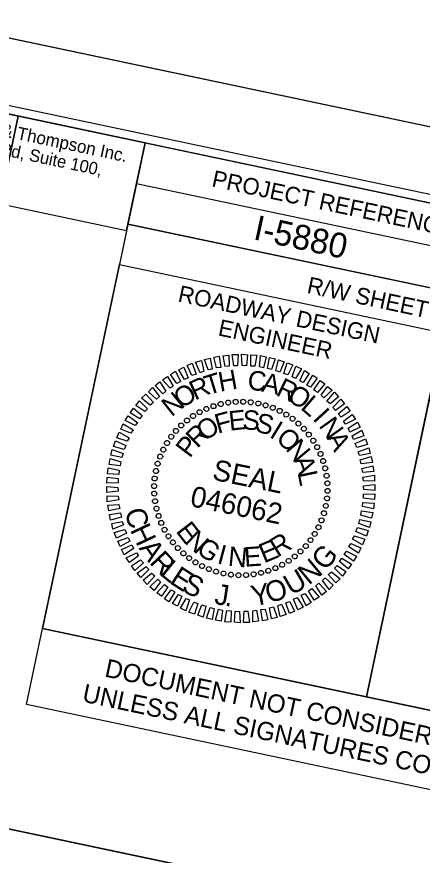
# Model space of a CAD drawing. Extents: x 1636389 to 1804395, y 659763 to 844521.
# Drawn here: x 1638006.9 to 1638129.5, y 843981.4 to 844234.9 of the extents above; entities that cross this region are included whole.
import ezdxf

# ---------------------------------------------------------------- set-up
doc = ezdxf.new("R2010")
doc.units = 0
for name, color, linetype in [('Default', 7, 'Continuous'), ('Old_Level_2', 7, 'Continuous'), ('Prop Dimension Text', 7, 'Continuous'), ('Sheet Clip Boundary CELL', 7, 'Continuous'), ('Sheet Cutting Line CELL', 7, 'Continuous'), ('Sheet Data Field CELL', 7, 'Continuous'), ('Sheet Plan CELL', 7, 'Continuous'), ('Sheet Plan Layout CELL', 7, 'Continuous'), ('Sheet Plot Border Inside CELL', 7, 'Continuous'), ('Sheet Plot Border Outside CELL', 7, 'Continuous'), ('Sheet Sticker Exception Certification CELL', 7, 'Continuous')]:
    doc.layers.add(name, color=color, linetype=linetype)

msp = doc.modelspace()

# ---------------------------------------------------------------- linework, layer by layer
at = {"layer": 'Old_Level_2'}
for p, q in [((1638068.56, 844117.84), (1638068.56, 844117.84)), ((1638070.77, 844118.28), (1638070.77, 844118.28)), ((1638073.04, 844118.49), (1638073.04, 844118.49)), ((1638075.38, 844118.48), (1638075.38, 844118.48)), ((1638077.65, 844118.37), (1638077.65, 844118.37)), ((1638079.92, 844118), (1638079.92, 844118)), ((1638062.15, 844115.42), (1638062.15, 844115.42)), ((1638064.19, 844116.37), (1638064.19, 844116.37)), ((1638066.36, 844117.18), (1638066.36, 844117.18)), ((1638082.15, 844117.43), (1638082.15, 844117.43)), ((1638084.29, 844116.66), (1638084.29, 844116.66)), ((1638086.37, 844115.79), (1638086.37, 844115.79)), ((1638058.32, 844112.89), (1638058.32, 844112.89)), ((1638060.16, 844114.19), (1638060.16, 844114.19)), ((1638088.39, 844114.67), (1638088.39, 844114.67)), ((1638090.27, 844113.36), (1638090.27, 844113.36)), ((1638056.6, 844111.35), (1638056.6, 844111.35)), ((1638092.09, 844111.96), (1638092.09, 844111.96)), ((1638093.7, 844110.33), (1638093.7, 844110.33)), ((1638053.57, 844107.92), (1638053.57, 844107.92)), ((1638054.97, 844109.73), (1638054.97, 844109.73)), ((1638095.24, 844108.6), (1638095.24, 844108.6)), ((1638052.26, 844106.04), (1638052.26, 844106.04)), ((1638096.54, 844106.76), (1638096.54, 844106.76)), ((1638051.14, 844104.01), (1638051.14, 844104.01)), ((1638097.77, 844104.78), (1638097.77, 844104.78)), ((1638098.72, 844102.74), (1638098.72, 844102.74)), ((1638050.27, 844101.94), (1638050.27, 844101.94)), ((1638099.54, 844100.57), (1638099.54, 844100.57)), ((1638048.92, 844097.57), (1638048.92, 844097.57)), ((1638049.5, 844099.8), (1638049.5, 844099.8)), ((1638100.19, 844098.37), (1638100.19, 844098.37)), ((1638048.55, 844095.29), (1638048.55, 844095.29)), ((1638100.63, 844096.16), (1638100.63, 844096.16)), ((1638048.45, 844093.03), (1638048.45, 844093.03)), ((1638074.64, 844092.29), (1638074.64, 844092.29)), ((1638100.84, 844093.89), (1638100.84, 844093.89)), ((1638048.44, 844090.69), (1638048.44, 844090.69)), ((1638100.83, 844091.55), (1638100.83, 844091.55)), ((1638048.65, 844088.41), (1638048.65, 844088.41)), ((1638100.73, 844089.28), (1638100.73, 844089.28)), ((1638049.09, 844086.2), (1638049.09, 844086.2)), ((1638099.78, 844084.78), (1638099.78, 844084.78)), ((1638100.36, 844087.01), (1638100.36, 844087.01)), ((1638049.74, 844084.01), (1638049.74, 844084.01)), ((1638099.01, 844082.63), (1638099.01, 844082.63)), ((1638050.56, 844081.83), (1638050.56, 844081.83)), ((1638051.51, 844079.8), (1638051.51, 844079.8)), ((1638098.14, 844080.56), (1638098.14, 844080.56)), ((1638052.74, 844077.81), (1638052.74, 844077.81)), ((1638097.02, 844078.54), (1638097.02, 844078.54)), ((1638054.04, 844075.97), (1638054.04, 844075.97)), ((1638094.31, 844074.84), (1638094.31, 844074.84)), ((1638095.71, 844076.65), (1638095.71, 844076.65)), ((1638055.58, 844074.25), (1638055.58, 844074.25)), ((1638057.19, 844072.62), (1638057.19, 844072.62)), ((1638092.68, 844073.23), (1638092.68, 844073.23)), ((1638059, 844071.22), (1638059, 844071.22)), ((1638060.89, 844069.91), (1638060.89, 844069.91)), ((1638089.12, 844070.38), (1638089.12, 844070.38)), ((1638090.95, 844071.69), (1638090.95, 844071.69)), ((1638062.91, 844068.78), (1638062.91, 844068.78)), ((1638064.99, 844067.92), (1638064.99, 844067.92)), ((1638067.13, 844067.15), (1638067.13, 844067.15)), ((1638082.92, 844067.39), (1638082.92, 844067.39)), ((1638085.09, 844068.21), (1638085.09, 844068.21)), ((1638087.13, 844069.16), (1638087.13, 844069.16)), ((1638069.36, 844066.57), (1638069.36, 844066.57)), ((1638071.63, 844066.2), (1638071.63, 844066.2)), ((1638073.9, 844066.1), (1638073.9, 844066.1)), ((1638076.24, 844066.08), (1638076.24, 844066.08)), ((1638078.51, 844066.3), (1638078.51, 844066.3)), ((1638080.72, 844066.74), (1638080.72, 844066.74))]:
    msp.add_line(p, q, dxfattribs=at)
for points in [[(1638075.08, 844129.44), (1638074.88, 844132.88), (1638076.6, 844132.72), (1638076.35, 844129.36)], [(1638062.34, 844127.29), (1638060.96, 844130.43), (1638062.71, 844130.95), (1638063.44, 844127.73)], [(1638064.78, 844128.12), (1638063.68, 844131.3), (1638065.4, 844131.72), (1638066, 844128.37)], [(1638067.25, 844128.77), (1638066.47, 844132), (1638068.12, 844132.33), (1638068.59, 844128.84)], [(1638069.92, 844129.13), (1638069.31, 844132.43), (1638070.99, 844132.6), (1638071.07, 844129.28)], [(1638072.51, 844129.33), (1638072.04, 844132.77), (1638073.85, 844132.81), (1638073.64, 844129.39)], [(1638077.61, 844129.29), (1638077.66, 844132.68), (1638079.44, 844132.56), (1638078.87, 844129.21)], [(1638080.23, 844129.06), (1638080.59, 844132.45), (1638082.28, 844132.08), (1638081.45, 844128.78)], [(1638082.68, 844128.55), (1638083.31, 844131.89), (1638085, 844131.52), (1638083.91, 844128.27)], [(1638085.23, 844127.92), (1638086.06, 844131.22), (1638087.69, 844130.59), (1638086.42, 844127.48)], [(1638057.6, 844125.25), (1638055.85, 844128.13), (1638057.44, 844128.95), (1638058.7, 844125.74)], [(1638059.84, 844126.43), (1638058.43, 844129.41), (1638059.95, 844130.14), (1638061.09, 844126.84)], [(1638087.62, 844127.05), (1638088.69, 844130.25), (1638090.34, 844129.68), (1638088.82, 844126.66)], [(1638090.13, 844125.99), (1638091.27, 844129.24), (1638092.94, 844128.5), (1638091.16, 844125.53)], [(1638092.48, 844124.86), (1638093.84, 844127.91), (1638095.34, 844127.09), (1638093.49, 844124.3)], [(1638053.22, 844122.56), (1638050.99, 844125.16), (1638052.49, 844126.1), (1638054.19, 844123.23)], [(1638055.25, 844124.04), (1638053.41, 844126.73), (1638054.87, 844127.73), (1638056.36, 844124.58)], [(1638094.62, 844123.51), (1638096.4, 844126.52), (1638097.73, 844125.64), (1638095.73, 844122.92)], [(1638049.15, 844119.28), (1638046.7, 844121.54), (1638047.95, 844122.85), (1638050, 844120.13)], [(1638051.05, 844120.94), (1638048.75, 844123.45), (1638050.13, 844124.57), (1638051.94, 844121.74)], [(1638096.75, 844122.1), (1638098.6, 844124.89), (1638100.06, 844123.87), (1638097.77, 844121.32)], [(1638098.89, 844120.47), (1638100.82, 844123.14), (1638102.2, 844121.98), (1638099.75, 844119.67)], [(1638047.22, 844117.51), (1638044.63, 844119.59), (1638045.93, 844120.84), (1638048.22, 844118.28)], [(1638100.64, 844118.71), (1638102.99, 844121.36), (1638104.13, 844120.03), (1638101.65, 844117.88)], [(1638045.57, 844115.53), (1638042.88, 844117.36), (1638043.95, 844118.81), (1638046.37, 844116.39)], [(1638102.46, 844116.78), (1638104.88, 844119.25), (1638106.01, 844117.87), (1638103.3, 844115.87)], [(1638044.1, 844113.36), (1638041.14, 844115.14), (1638042.21, 844116.59), (1638044.83, 844114.39)], [(1638104.11, 844114.82), (1638106.72, 844117.1), (1638107.72, 844115.63), (1638104.94, 844113.86)], [(1638042.65, 844111.29), (1638039.64, 844112.81), (1638040.61, 844114.28), (1638043.42, 844112.26)], [(1638105.63, 844112.67), (1638108.29, 844114.68), (1638109.29, 844113.21), (1638106.24, 844111.71)], [(1638041.42, 844108.97), (1638038.36, 844110.23), (1638039.04, 844111.86), (1638042.04, 844109.97)], [(1638107.08, 844110.49), (1638109.88, 844112.36), (1638110.7, 844110.77), (1638107.61, 844109.33)], [(1638040.29, 844106.62), (1638037.18, 844107.63), (1638037.87, 844109.31), (1638040.91, 844107.63)], [(1638108.25, 844108.19), (1638111.17, 844109.88), (1638111.87, 844108.21), (1638108.68, 844107.1)], [(1638039.39, 844104.08), (1638036.16, 844105), (1638036.69, 844106.71), (1638039.88, 844105.26)], [(1638109.19, 844105.84), (1638112.28, 844107.28), (1638112.97, 844105.56), (1638109.72, 844104.68)], [(1638038.68, 844101.66), (1638035.35, 844102.39), (1638035.77, 844104.06), (1638039.01, 844102.87)], [(1638110.1, 844103.33), (1638113.32, 844104.59), (1638113.69, 844102.87), (1638110.54, 844102.24)], [(1638038.15, 844099.1), (1638034.78, 844099.57), (1638035.1, 844101.32), (1638038.38, 844100.33)], [(1638110.72, 844100.92), (1638114.04, 844101.9), (1638114.4, 844100.13), (1638111.02, 844099.7)], [(1638037.72, 844096.52), (1638034.3, 844096.73), (1638034.52, 844098.5), (1638037.84, 844097.77)], [(1638111.19, 844098.34), (1638114.58, 844099.09), (1638114.85, 844097.39), (1638111.51, 844097.16)], [(1638037.56, 844093.99), (1638034.09, 844093.9), (1638034.26, 844095.67), (1638037.59, 844095.27)], [(1638111.56, 844095.72), (1638115.07, 844096.28), (1638115.06, 844094.53), (1638111.71, 844094.57)], [(1638037.57, 844091.44), (1638034.15, 844091.07), (1638034.16, 844092.87), (1638037.46, 844092.58)], [(1638111.71, 844093.13), (1638115.13, 844093.51), (1638115.12, 844091.7), (1638111.82, 844092)], [(1638037.72, 844088.86), (1638034.21, 844088.29), (1638034.22, 844090.04), (1638037.56, 844090)], [(1638111.71, 844090.58), (1638115.19, 844090.68), (1638115.02, 844088.9), (1638111.69, 844089.31)], [(1638038.09, 844086.24), (1638034.7, 844085.49), (1638034.43, 844087.19), (1638037.77, 844087.41)], [(1638111.56, 844088.05), (1638114.98, 844087.84), (1638114.76, 844086.08), (1638111.44, 844086.8)], [(1638038.56, 844083.65), (1638035.24, 844082.67), (1638034.88, 844084.44), (1638038.26, 844084.88)], [(1638111.13, 844085.48), (1638114.5, 844085.01), (1638114.18, 844083.26), (1638110.9, 844084.24)], [(1638039.18, 844081.25), (1638035.96, 844079.99), (1638035.59, 844081.7), (1638038.74, 844082.34)], [(1638110.6, 844082.91), (1638113.92, 844082.19), (1638113.51, 844080.51), (1638110.27, 844081.7)], [(1638040.09, 844078.74), (1638037, 844077.29), (1638036.31, 844079.02), (1638039.56, 844079.9)], [(1638109.89, 844080.5), (1638113.12, 844079.57), (1638112.59, 844077.86), (1638109.4, 844079.31)], [(1638041.03, 844076.38), (1638038.11, 844074.69), (1638037.41, 844076.36), (1638040.6, 844077.47)], [(1638108.99, 844077.95), (1638112.1, 844076.94), (1638111.41, 844075.26), (1638108.37, 844076.95)], [(1638042.2, 844074.09), (1638039.4, 844072.21), (1638038.58, 844073.8), (1638041.67, 844075.25)], [(1638107.86, 844075.61), (1638110.92, 844074.35), (1638110.24, 844072.72), (1638107.24, 844074.61)], [(1638043.65, 844071.9), (1638040.99, 844069.9), (1638039.99, 844071.36), (1638043.04, 844072.87)], [(1638106.62, 844073.29), (1638109.64, 844071.77), (1638108.67, 844070.3), (1638105.86, 844072.31)], [(1638045.17, 844069.76), (1638042.56, 844067.48), (1638041.56, 844068.94), (1638044.34, 844070.71)], [(1638105.17, 844071.22), (1638108.14, 844069.44), (1638107.07, 844067.99), (1638104.45, 844070.18)], [(1638046.82, 844067.8), (1638044.39, 844065.33), (1638043.27, 844066.71), (1638045.98, 844068.7)], [(1638102.06, 844067.06), (1638104.65, 844064.98), (1638103.35, 844063.74), (1638101.06, 844066.29)], [(1638103.71, 844069.04), (1638106.4, 844067.21), (1638105.33, 844065.76), (1638102.91, 844068.18)], [(1638048.64, 844065.86), (1638046.29, 844063.22), (1638045.15, 844064.55), (1638047.63, 844066.69)], [(1638050.39, 844064.1), (1638048.45, 844061.43), (1638047.08, 844062.59), (1638049.53, 844064.9)], [(1638100.13, 844065.29), (1638102.58, 844063.03), (1638101.33, 844061.72), (1638099.28, 844064.44)], [(1638052.53, 844062.48), (1638050.68, 844059.68), (1638049.22, 844060.7), (1638051.51, 844063.25)], [(1638096.06, 844062.01), (1638098.29, 844059.42), (1638096.79, 844058.47), (1638095.09, 844061.34)], [(1638098.23, 844063.63), (1638100.53, 844061.13), (1638099.15, 844060), (1638097.33, 844062.84)], [(1638054.66, 844061.07), (1638052.88, 844058.05), (1638051.55, 844058.94), (1638053.55, 844061.65)], [(1638056.8, 844059.71), (1638055.44, 844056.67), (1638053.94, 844057.48), (1638055.79, 844060.27)], [(1638094.03, 844060.53), (1638095.87, 844057.85), (1638094.41, 844056.84), (1638092.92, 844059.99)], [(1638059.15, 844058.58), (1638058.01, 844055.34), (1638056.34, 844056.08), (1638058.12, 844059.04)], [(1638061.66, 844057.53), (1638060.59, 844054.33), (1638058.94, 844054.9), (1638060.46, 844057.91)], [(1638064.05, 844056.66), (1638063.22, 844053.35), (1638061.59, 844053.98), (1638062.86, 844057.09)], [(1638086.94, 844057.28), (1638088.32, 844054.15), (1638086.57, 844053.62), (1638085.84, 844056.84)], [(1638089.44, 844058.14), (1638090.85, 844055.17), (1638089.33, 844054.44), (1638088.19, 844057.74)], [(1638091.68, 844059.32), (1638093.43, 844056.44), (1638091.84, 844055.62), (1638090.58, 844058.83)], [(1638066.59, 844056.02), (1638065.97, 844052.68), (1638064.28, 844053.05), (1638065.37, 844056.3)], [(1638069.05, 844055.51), (1638068.69, 844052.12), (1638067, 844052.49), (1638067.83, 844055.79)], [(1638071.67, 844055.29), (1638071.62, 844051.89), (1638069.84, 844052.01), (1638070.41, 844055.36)], [(1638074.19, 844055.14), (1638074.4, 844051.69), (1638072.68, 844051.86), (1638072.93, 844055.21)], [(1638076.77, 844055.24), (1638077.24, 844051.8), (1638075.43, 844051.77), (1638075.64, 844055.19)], [(1638079.36, 844055.45), (1638079.97, 844052.14), (1638078.29, 844051.98), (1638078.21, 844055.29)], [(1638082.03, 844055.8), (1638082.81, 844052.57), (1638081.15, 844052.24), (1638080.69, 844055.73)], [(1638084.49, 844056.46), (1638085.6, 844053.27), (1638083.87, 844052.85), (1638083.28, 844056.21)]]:
    msp.add_lwpolyline(points, close=True, dxfattribs=at)
for centre, major_axis in [((1638066.35, 844117.17), (-0.238, 0.714)), ((1638068.55, 844117.8), (-0.175, 0.732)), ((1638070.8, 844118.23), (-0.11, 0.745)), ((1638073.07, 844118.47), (-0.045, 0.752)), ((1638075.36, 844118.5), (0.021, 0.753)), ((1638077.64, 844118.34), (0.086, 0.748)), ((1638079.9, 844117.98), (0.151, 0.738)), ((1638082.12, 844117.43), (0.215, 0.722)), ((1638062.15, 844115.35), (-0.358, 0.662)), ((1638064.21, 844116.35), (-0.299, 0.691)), ((1638084.28, 844116.68), (0.277, 0.7)), ((1638086.37, 844115.74), (0.337, 0.673)), ((1638088.37, 844114.63), (0.394, 0.641)), ((1638058.34, 844112.83), (-0.468, 0.59)), ((1638060.19, 844114.18), (-0.415, 0.628)), ((1638090.27, 844113.35), (0.449, 0.605)), ((1638092.04, 844111.91), (0.5, 0.563)), ((1638055.02, 844109.69), (-0.563, 0.5)), ((1638056.61, 844111.33), (-0.518, 0.547)), ((1638093.69, 844110.32), (0.547, 0.518)), ((1638053.58, 844107.91), (-0.605, 0.449)), ((1638095.19, 844108.59), (0.59, 0.468)), ((1638096.53, 844106.74), (0.628, 0.415)), ((1638052.29, 844106.02), (-0.641, 0.394)), ((1638097.71, 844104.77), (0.662, 0.358)), ((1638050.25, 844101.93), (-0.7, 0.277)), ((1638051.18, 844104.02), (-0.673, 0.337)), ((1638098.71, 844102.71), (0.691, 0.299)), ((1638049.5, 844099.77), (-0.722, 0.215)), ((1638099.52, 844100.58), (0.714, 0.238)), ((1638048.95, 844097.55), (-0.738, 0.151)), ((1638100.15, 844098.38), (0.732, 0.175)), ((1638048.58, 844095.29), (-0.748, 0.086)), ((1638100.58, 844096.13), (0.745, 0.11)), ((1638048.42, 844093.01), (-0.753, 0.021)), ((1638100.82, 844093.86), (0.752, 0.045)), ((1638100.86, 844091.57), (0.753, -0.021)), ((1638048.46, 844090.72), (-0.752, -0.045)), ((1638100.7, 844089.28), (0.748, -0.086)), ((1638048.7, 844088.44), (-0.745, -0.11)), ((1638100.33, 844087.03), (0.738, -0.151)), ((1638049.13, 844086.2), (-0.732, -0.175)), ((1638049.76, 844084), (-0.714, -0.238)), ((1638099.78, 844084.81), (0.722, -0.215)), ((1638050.57, 844081.86), (-0.691, -0.299)), ((1638099.03, 844082.64), (0.7, -0.277)), ((1638051.57, 844079.8), (-0.662, -0.358)), ((1638098.1, 844080.55), (0.673, -0.337)), ((1638052.75, 844077.84), (-0.628, -0.415)), ((1638095.7, 844076.66), (0.605, -0.449)), ((1638096.99, 844078.55), (0.641, -0.394)), ((1638054.09, 844075.99), (-0.59, -0.468)), ((1638055.59, 844074.26), (-0.547, -0.518)), ((1638094.26, 844074.88), (0.563, -0.5)), ((1638057.24, 844072.67), (-0.5, -0.563)), ((1638059.01, 844071.22), (-0.449, -0.605)), ((1638090.94, 844071.74), (0.468, -0.59)), ((1638092.67, 844073.24), (0.518, -0.547)), ((1638060.91, 844069.94), (-0.394, -0.641)), ((1638062.91, 844068.83), (-0.337, -0.673)), ((1638087.13, 844069.22), (0.358, -0.662)), ((1638089.09, 844070.4), (0.415, -0.628)), ((1638065, 844067.9), (-0.277, -0.7)), ((1638067.16, 844067.15), (-0.215, -0.722)), ((1638069.38, 844066.59), (-0.151, -0.738)), ((1638071.64, 844066.23), (-0.086, -0.748)), ((1638078.48, 844066.34), (0.11, -0.745)), ((1638080.73, 844066.78), (0.175, -0.732)), ((1638082.93, 844067.4), (0.238, -0.714)), ((1638085.07, 844068.22), (0.299, -0.691)), ((1638073.92, 844066.07), (-0.021, -0.753)), ((1638076.21, 844066.11), (0.045, -0.752))]:
    msp.add_ellipse(centre, major_axis=major_axis, ratio=0.999708, dxfattribs=at)
at = {"layer": 'Prop Dimension Text'}
msp.add_lwpolyline([(1637893.3, 844201.3), (1638040.08, 844170.28), (1638045.68, 844196.77), (1637898.89, 844227.79)], close=True, dxfattribs=at)
at = {"layer": 'Sheet Clip Boundary CELL'}
msp.add_lwpolyline([(1636605.88, 843427.4), (1637975.74, 843138.4), (1637933.22, 843216.08), (1637972.57, 843309.02), (1638006.91, 843302.19), (1638028.95, 843389.18), (1638110.62, 843766.5), (1638114.85, 843806.98), (1638084.44, 843843.65), (1637963.65, 843997.92), (1638007.31, 844204.85), (1636822.64, 844454.79)], close=True, dxfattribs=at)
at = {"layer": 'Sheet Cutting Line CELL'}
msp.add_line((1638262.69, 844173.95), (1636615.46, 844521.48), dxfattribs=at)
at = {"layer": 'Sheet Plan CELL'}
for p, q in [((1638043.08, 844184.49), (1638238.82, 844143.18)), ((1638040.5, 844172.22), (1638037.92, 844160)), ((1638040.5, 844172.22), (1638236.24, 844130.95)), ((1638040.5, 844172.22), (1638236.24, 844130.95)), ((1638135.82, 844139.35), (1638112.61, 844029.31))]:
    msp.add_line(p, q, dxfattribs=at)
for points in [[(1638241.44, 844155.45), (1636773.71, 844465.11), (1636556.96, 843437.72), (1638024.67, 843128.08)], [(1636556.96, 843437.72), (1636773.69, 844465.09), (1638045.68, 844196.77), (1638014.71, 844049.94), (1638210.44, 844008.63), (1638024.67, 843128.08)], [(1638045.68, 844196.77), (1638241.44, 844155.45), (1638236.24, 844130.95), (1638040.5, 844172.22)], [(1638037.92, 844160), (1638135.82, 844139.35), (1638112.59, 844029.26), (1638014.71, 844049.94)], [(1638135.82, 844139.35), (1638233.65, 844118.72), (1638210.44, 844008.63), (1638112.59, 844029.26)]]:
    msp.add_lwpolyline(points, close=True, dxfattribs=at)
at = {"layer": 'Sheet Plan Layout CELL'}
for points in [[(1636773.69, 844465.09), (1636556.96, 843437.72), (1638024.65, 843128.08), (1638197.75, 843948.53), (1637963.65, 843997.92), (1638007.31, 844204.85)], [(1637963.65, 843997.92), (1638197.77, 843948.52), (1638241.46, 844155.45), (1638007.31, 844204.85)]]:
    msp.add_lwpolyline(points, close=True, dxfattribs=at)
at = {"layer": 'Sheet Plot Border Inside CELL'}
msp.add_lwpolyline([(1636406.26, 843466.95), (1638036.37, 843123.05), (1638254.16, 844155.31), (1636624.05, 844499.23)], close=True, dxfattribs=at)
at = {"layer": 'Sheet Plot Border Outside CELL'}
msp.add_lwpolyline([(1636389.41, 843450.07), (1638036.65, 843102.54), (1638262.69, 844173.95), (1636615.46, 844521.48)], close=True, dxfattribs=at)
at = {"layer": 'Sheet Sticker Exception Certification CELL'}
for p, q in [((1638009.86, 844026.94), (1638014.71, 844049.94)), ((1638009.86, 844026.94), (1638014.71, 844049.94)), ((1638014.71, 844049.94), (1638210.44, 844008.64)), ((1638014.71, 844049.94), (1638210.44, 844008.64)), ((1638205.59, 843985.65), (1638009.86, 844026.94)), ((1638205.59, 843985.65), (1638009.86, 844026.94))]:
    msp.add_line(p, q, dxfattribs=at)

# ---------------------------------------------------------------- texts
at = {"layer": 'Default'}
for s, rotation, p in [('C', 285.6274, (1638039.44, 844085.48)), ('H', 295.0712, (1638041.03, 844079.79)), ('A', 304.911, (1638043.66, 844074.23)), ('G', 50.2273, (1638100.23, 844067.15)), ('R', 313.6236, (1638046.75, 844069.75)), ('L', 320.9958, (1638049.87, 844066.35)), ('N', 39.6564, (1638095.18, 844062.88)), ('E', 327.18, (1638052.8, 844063.84)), ('U', 29.8623, (1638089.89, 844059.81)), ('S', 334.1867, (1638056.43, 844061.38)), ('O', 18.4688, (1638083.17, 844057.44)), ('J', 351.4596, (1638066.43, 844057.37)), ('Y', 10.6701, (1638078.37, 844056.61)), ('.', 356.6415, (1638069.61, 844056.77))]:
    msp.add_text(s, height=6.27, rotation=rotation, dxfattribs=at).set_placement(p)
at = {"layer": 'Old_Level_2'}
for s, height, rotation, p in [('H', 5.9, 10.047, (1638068.34, 844121.5)), ('C', 5.9, 355.6474, (1638076.53, 844122.09)), ('R', 5.9, 24.448, (1638060.76, 844118.81)), ('T', 5.9, 17.2473, (1638064.68, 844120.42)), ('A', 5.9, 348.4478, (1638080.65, 844121.64)), ('R', 5.9, 334.0486, (1638084.93, 844120.63)), ('O', 5.9, 31.6493, (1638056.62, 844116.29)), ('O', 5.9, 326.8487, (1638088.23, 844119.22)), ('N', 5.9, 38.851, (1638053.7, 844113.75)), ('L', 5.9, 319.6484, (1638092.4, 844116.47)), ('F', 5.9, 15.3946, (1638067.67, 844108.8)), ('E', 5.9, 6.0386, (1638071.25, 844109.73)), ('S', 5.9, 356.6831, (1638074.99, 844110.15)), ('I', 5.9, 312.4477, (1638096.1, 844113.23)), ('O', 5.9, 34.1088, (1638063.71, 844106.4)), ('S', 5.9, 347.3279, (1638078.7, 844109.51)), ('I', 5.9, 328.6171, (1638082.99, 844107.96)), ('N', 5.9, 305.2464, (1638098.01, 844111.22)), ('R', 5.9, 43.4672, (1638061.44, 844104.22)), ('O', 5.9, 319.261, (1638084.91, 844106.86)), ('P', 5.9, 52.8264, (1638059.18, 844101.24)), ('A', 5.9, 298.0447, (1638100.48, 844107.62)), ('N', 5.9, 309.9041, (1638087.97, 844104.16)), ('SEAL', 6.273, 348.4275, (1638065.73, 844095.01)), ('A', 5.9, 291.1878, (1638090.4, 844100.94)), ('L', 5.9, 281.8284, (1638091.75, 844097.02)), ('046062', 6.275, 348.4275, (1638059.01, 844086.99)), ('E', 5.9, 307.7044, (1638054.78, 844079.35)), ('N', 5.9, 317.0615, (1638057.34, 844075.99)), ('R', 5.9, 31.9089, (1638085.73, 844071.33)), ('G', 5.9, 326.4178, (1638060.82, 844072.95)), ('I', 5.9, 345.1287, (1638067.19, 844069.74)), ('N', 5.9, 354.4839, (1638070.6, 844068.94)), ('E', 5.9, 3.8393, (1638075.81, 844068.61)), ('E', 5.9, 22.5516, (1638081.63, 844069.6))]:
    msp.add_text(s, height=height, rotation=rotation, dxfattribs=at).set_placement(p)
at = {"layer": 'Prop Dimension Text'}
for s, height, p in [('Johnson, Mirmiran, & Thompson Inc.', 3.8334, (1637957.91, 844208.23)), ('4700 Falls of Neuse Rd, Suite 100, ', 3.7239, (1637956.75, 844202.73))]:
    msp.add_text(s, height=height, rotation=348.0661, dxfattribs=at).set_placement(p)
at = {"layer": 'Sheet Data Field CELL'}
msp.add_text('I-5880', height=7.5, rotation=347.8006, dxfattribs=at).set_placement((1638078.13, 844167.64))
at = {"layer": 'Sheet Plan CELL'}
for s, height, p in [('PROJECT REFERENCE NO.', 5.0001, (1638065.6, 844183.65)), ('R/W SHEET NO.', 5.0001, (1638094.38, 844151.46)), ('ROADWAY DESIGN', 5.0001, (1638055.37, 844148.86)), ('ENGINEER', 5, (1638067.5, 844138.6))]:
    msp.add_text(s, height=height, rotation=348.0867, dxfattribs=at).set_placement(p)
at = {"layer": 'Sheet Sticker Exception Certification CELL'}
for s, p in [('DOCUMENT NOT CONSIDERED FINAL', (1638033.2, 844035.46)), ('DOCUMENT NOT CONSIDERED FINAL', (1638033.2, 844035.46)), ('UNLESS ALL SIGNATURES COMPLETED', (1638026.42, 844027.9)), ('UNLESS ALL SIGNATURES COMPLETED', (1638026.42, 844027.9))]:
    msp.add_text(s, height=5.5, rotation=348.0867, dxfattribs=at).set_placement(p)

doc.saveas('drawing.dxf')
